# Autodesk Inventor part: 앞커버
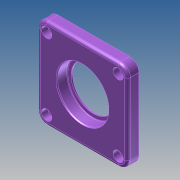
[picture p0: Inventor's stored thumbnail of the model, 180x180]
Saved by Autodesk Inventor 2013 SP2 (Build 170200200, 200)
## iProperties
Created: 2025-06
Part Number: 앞커버
Material: Generic
Document SubType Name: Modeling
Designer: i
Density: 1 g/cm^3
Author: i
변환 표준: STEP AP214IS
전처리기: Build: 200, Release: 2013 SP2 Update 6 - Date: Thu 07/17/2014
전송 단위: 밀리미터
불확실성: 0.01
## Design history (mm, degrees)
node "앞커버1"
node "솔리드1"
node "기준1"
